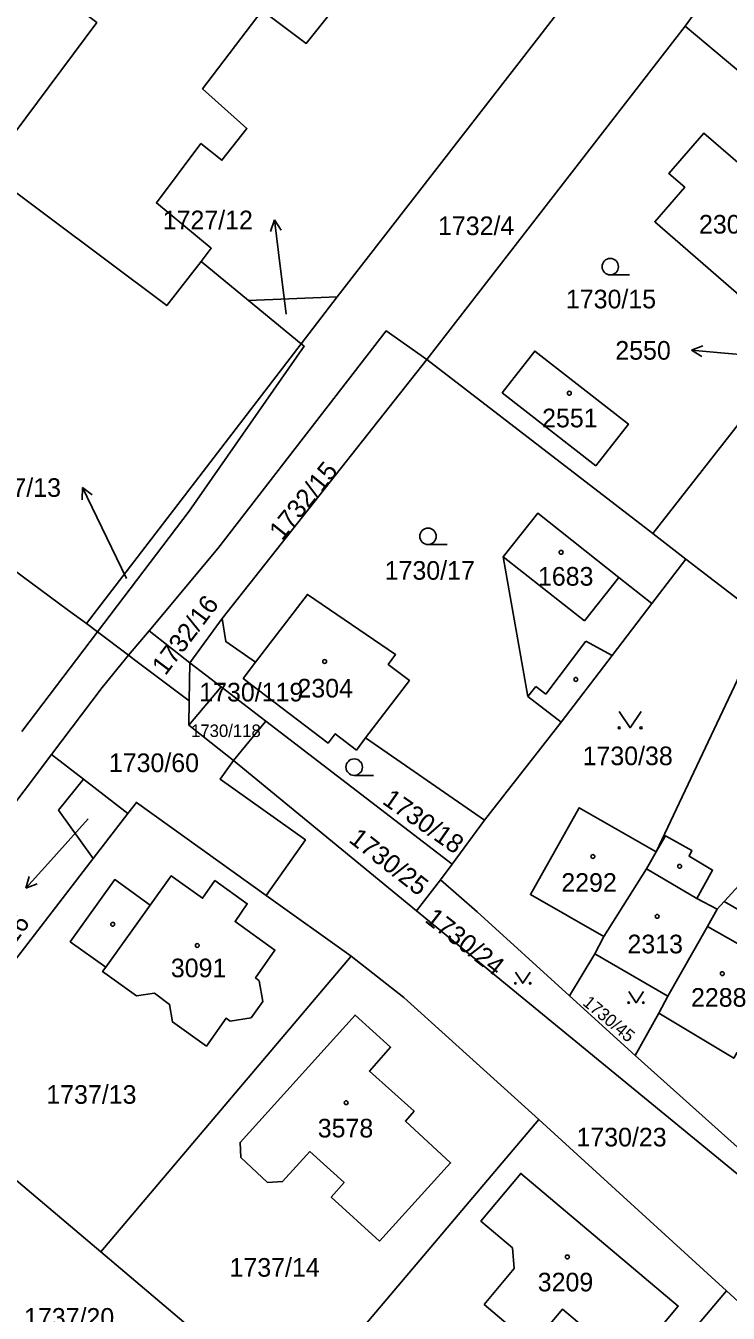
# Model space of a CAD drawing. Extents: x -679220 to -673243, y -1075091 to -1066557.
# Drawn here: x -676884 to -676820, y -1072173.6 to -1072056.2 of the extents above; entities that cross this region are included whole.
import ezdxf

# ---------------------------------------------------------------- set-up
doc = ezdxf.new("R2010")
doc.units = 0
for name, color, linetype in [('Hranice parcel', 7, 'Continuous'), ('Parcelní čísla', 7, 'Continuous'), ('Pop  PČ popisy', 7, 'Continuous'), ('Vnitřní kresba', 7, 'Continuous'), ('Značky budov', 7, 'Continuous'), ('Značky kultur', 7, 'Continuous')]:
    doc.layers.add(name, color=color, linetype=linetype)

msp = doc.modelspace()

# ---------------------------------------------------------------- linework, layer by layer
at = {"layer": 'Hranice parcel'}
for p, q in [((-676823.88, -1072056.2), (-676821.06, -1072052.26)), ((-676847.45, -1072086.6), (-676823.88, -1072056.2)), ((-676803.88, -1072073.07), (-676823.88, -1072056.2)), ((-676868.02, -1072077.66), (-676863.69, -1072081.21)), ((-676863.69, -1072081.21), (-676855.6, -1072080.89)), ((-676858.9, -1072085.15), (-676855.6, -1072080.89)), ((-676858.9, -1072085.15), (-676863.69, -1072081.21)), ((-676878.47, -1072110.68), (-676858.9, -1072085.15)), ((-676866.08, -1072110.22), (-676847.45, -1072086.6)), ((-676847.45, -1072086.6), (-676826.85, -1072102.46)), ((-676816.81, -1072089.62), (-676826.85, -1072102.46)), ((-676826.85, -1072102.46), (-676823.82, -1072104.8)), ((-676823.82, -1072104.8), (-676826.92, -1072108.84)), ((-676823.82, -1072104.8), (-676816.58, -1072110.38)), ((-676869.04, -1072114.25), (-676866.08, -1072110.22)), ((-676826.54, -1072131.48), (-676816.58, -1072110.38)), ((-676877.46, -1072111.44), (-676884.36, -1072120.53)), ((-676877.46, -1072111.44), (-676878.47, -1072110.68)), ((-676874.63, -1072113.57), (-676877.46, -1072111.44)), ((-676874.63, -1072113.57), (-676872.76, -1072111.33)), ((-676872.76, -1072111.33), (-676869.04, -1072114.25)), ((-676869.04, -1072114.25), (-676869.1, -1072117.73)), ((-676866.18, -1072116.45), (-676869.04, -1072114.25)), ((-676866.18, -1072116.45), (-676869.14, -1072119.94)), ((-676862.11, -1072119.58), (-676866.18, -1072116.45)), ((-676869.14, -1072119.94), (-676869.1, -1072117.73)), ((-676862.11, -1072119.58), (-676865.06, -1072123.15)), ((-676845.13, -1072132.63), (-676862.11, -1072119.58)), ((-676835.2, -1072119.66), (-676842.17, -1072128.6)), ((-676820.33, -1072136.02), (-676805.06, -1072119.28)), ((-676865.06, -1072123.15), (-676869.14, -1072119.94)), ((-676853.02, -1072121.11), (-676842.17, -1072128.6)), ((-676878.73, -1072124.88), (-676881.65, -1072122.62)), ((-676848.37, -1072136.87), (-676865.06, -1072123.15)), ((-676878.73, -1072124.88), (-676874.69, -1072128)), ((-676877.85, -1072132.1), (-676874.69, -1072128)), ((-676842.17, -1072128.6), (-676845.13, -1072132.63)), ((-676894.29, -1072153.48), (-676877.85, -1072132.1)), ((-676846.2, -1072134.04), (-676845.13, -1072132.63)), ((-676846.2, -1072134.04), (-676848.37, -1072136.87)), ((-676862.08, -1072135.47), (-676854.34, -1072141.02)), ((-676820.33, -1072136.02), (-676820.97, -1072136.72)), ((-676793.27, -1072182.15), (-676848.37, -1072136.87)), ((-676831.31, -1072139.22), (-676832.14, -1072140.8)), ((-676834.43, -1072144.62), (-676832.14, -1072140.8)), ((-676832.14, -1072140.8), (-676825.48, -1072144.67)), ((-676877.14, -1072167.98), (-676854.34, -1072141.02)), ((-676828.45, -1072150.07), (-676834.43, -1072144.62)), ((-676825.48, -1072144.67), (-676826.29, -1072146.21)), ((-676826.29, -1072146.21), (-676828.45, -1072150.07)), ((-676817.98, -1072159.47), (-676828.45, -1072150.07)), ((-676877.14, -1072167.98), (-676894.29, -1072153.48)), ((-676859.84, -1072182.62), (-676837.24, -1072155.91)), ((-676837.24, -1072155.91), (-676820.13, -1072171.54)), ((-676861.6, -1072181.13), (-676877.14, -1072167.98)), ((-676820.13, -1072171.54), (-676842.16, -1072197.58)), ((-676820.13, -1072171.54), (-676804.75, -1072185.58))]:
    msp.add_line(p, q, dxfattribs=at)
for points in [[(-676868.02, -1072077.66), (-676867.08, -1072076.45), (-676872.09, -1072072.31), (-676868.03, -1072066.91), (-676866.12, -1072068.42), (-676863.83, -1072065.54), (-676867.87, -1072061.91), (-676862.44, -1072054.78), (-676858.43, -1072057.77), (-676851.76, -1072049.4), (-676847.29, -1072052.86), (-676843.34, -1072047.64), (-676857.56, -1072036.75), (-676866.88, -1072047.56), (-676883.62, -1072035.08), (-676891.33, -1072045.54), (-676877.52, -1072055.87), (-676884, -1072064.55)], [(-676855.6, -1072080.89), (-676837.24, -1072057.21), (-676831.2, -1072049.36)], [(-676884, -1072064.55), (-676887.59, -1072069.36), (-676871.15, -1072081.68), (-676868.02, -1072077.66)], [(-676818.55, -1072081.08), (-676812.62, -1072074.24), (-676816.12, -1072071.21), (-676815.04, -1072069.96), (-676817.81, -1072067.56), (-676818.89, -1072068.81), (-676822.18, -1072065.95), (-676825.37, -1072069.64), (-676823.93, -1072070.88), (-676826.67, -1072074.03), (-676818.55, -1072081.08)], [(-676919.29, -1072078.44), (-676919.07, -1072080.61), (-676880.11, -1072109.47), (-676878.47, -1072110.68)], [(-676872.76, -1072111.33), (-676866.49, -1072103.82), (-676851.15, -1072083.99), (-676847.45, -1072086.6)], [(-676858.9, -1072085.15), (-676858.61, -1072085.38), (-676869.11, -1072100.43), (-676877.46, -1072111.44)], [(-676832.03, -1072096.29), (-676829.07, -1072092.48), (-676837.6, -1072085.83), (-676840.56, -1072089.63), (-676832.03, -1072096.29)], [(-676826.92, -1072108.84), (-676829.93, -1072106.46), (-676837.33, -1072100.61), (-676840.48, -1072104.59), (-676838.23, -1072117.32), (-676835.2, -1072119.66)], [(-676853.02, -1072121.11), (-676849.03, -1072115.87), (-676850.96, -1072114.4), (-676850.28, -1072113.51), (-676858.32, -1072108.01), (-676863.04, -1072114.2)], [(-676826.92, -1072108.84), (-676830.56, -1072113.6), (-676835.2, -1072119.66)], [(-676866.08, -1072110.22), (-676865.76, -1072112.32), (-676863.04, -1072114.2)], [(-676881.65, -1072122.62), (-676877.03, -1072116.51), (-676874.63, -1072113.57)], [(-676869.1, -1072117.73), (-676874.09, -1072113.98), (-676874.63, -1072113.57)], [(-676863.04, -1072114.2), (-676864.17, -1072115.68), (-676856.44, -1072121.58), (-676855.79, -1072120.73), (-676853.86, -1072122.21), (-676853.02, -1072121.11)], [(-676881.65, -1072122.62), (-676886.67, -1072129.25), (-676891.41, -1072136.94), (-676900.48, -1072148.99), (-676901.52, -1072159.25), (-676900.62, -1072162.14)], [(-676865.06, -1072123.15), (-676866.28, -1072124.86), (-676858.5, -1072130.41), (-676862.08, -1072135.47)], [(-676877.85, -1072132.1), (-676881.01, -1072127.7), (-676878.73, -1072124.88)], [(-676874.69, -1072128), (-676873.91, -1072126.99), (-676862.08, -1072135.47)], [(-676826.54, -1072131.48), (-676833.54, -1072127.48), (-676838, -1072135.39), (-676831.31, -1072139.22)], [(-676820.97, -1072136.72), (-676822.84, -1072135.74), (-676821.4, -1072133.15), (-676823.54, -1072131.89), (-676823.29, -1072131.36), (-676825.68, -1072130.03), (-676826.54, -1072131.48)], [(-676831.31, -1072139.22), (-676827.43, -1072133.04), (-676826.54, -1072131.48)], [(-676872.26, -1072144.39), (-676870.89, -1072145.41), (-676870.62, -1072147), (-676867.53, -1072149.2), (-676865.73, -1072146.67), (-676865.35, -1072146.95), (-676863.46, -1072146.64), (-676862.38, -1072145.13), (-676862.71, -1072143.26), (-676863.04, -1072142.99), (-676861.28, -1072140.46), (-676864.92, -1072137.85), (-676863.8, -1072136.23), (-676866.76, -1072134.12), (-676867.88, -1072135.73), (-676870.73, -1072133.68), (-676872.64, -1072136.36), (-676875.89, -1072134.03), (-676879.94, -1072139.69), (-676876.7, -1072142.02), (-676876.99, -1072142.42), (-676873.9, -1072144.61), (-676872.26, -1072144.39)], [(-676834.43, -1072144.62), (-676842.84, -1072136.96), (-676846.2, -1072134.04)], [(-676826.29, -1072146.21), (-676819.47, -1072150.32), (-676819.19, -1072149.82), (-676815.71, -1072151.78), (-676809.26, -1072140.45), (-676813.74, -1072137.86), (-676814.6, -1072139.34), (-676820.33, -1072136.02)], [(-676820.97, -1072136.72), (-676821.85, -1072138.29), (-676825.48, -1072144.67)], [(-676854.34, -1072141.02), (-676849.52, -1072144.78), (-676837.24, -1072155.91)], [(-676848.59, -1072155.14), (-676849.39, -1072156.05), (-676845.28, -1072159.86), (-676851.75, -1072166.99), (-676856.15, -1072162.98), (-676854.98, -1072161.64), (-676858.11, -1072158.83), (-676860.58, -1072161.56), (-676861.95, -1072161.64), (-676864.38, -1072159.38), (-676864.46, -1072158), (-676853.97, -1072146.38), (-676850.74, -1072149.31), (-676852.67, -1072151.48), (-676848.59, -1072155.14)], [(-676842.21, -1072172.77), (-676839.47, -1072169.5), (-676839.63, -1072167.61), (-676842.51, -1072165.16), (-676838.87, -1072160.82), (-676824.52, -1072172.92), (-676829.02, -1072178.3), (-676835.07, -1072173.19), (-676837.85, -1072176.48), (-676842.21, -1072172.77)]]:
    msp.add_lwpolyline(points, dxfattribs=at)
at = {"layer": 'Pop  PČ popisy'}
for p, q in [((-676861.32, -1072073.87), (-676861.69, -1072074.93)), ((-676860.95, -1072076.85), (-676861.32, -1072073.87)), ((-676861.32, -1072073.87), (-676860.7, -1072074.8)), ((-676860.26, -1072082.47), (-676860.95, -1072076.85)), ((-676823.31, -1072085.75), (-676822.27, -1072085.34)), ((-676820.32, -1072086.01), (-676823.31, -1072085.75)), ((-676823.31, -1072085.75), (-676822.36, -1072086.33)), ((-676818.14, -1072086.2), (-676820.32, -1072086.01)), ((-676878.83, -1072098.27), (-676878.84, -1072099.39)), ((-676877.51, -1072100.97), (-676878.83, -1072098.27)), ((-676878.83, -1072098.27), (-676877.94, -1072098.95)), ((-676874.82, -1072106.56), (-676877.51, -1072100.97)), ((-676878.31, -1072128.47), (-676881.98, -1072132.59)), ((-676881.98, -1072132.59), (-676883.99, -1072134.82)), ((-676883.99, -1072134.82), (-676883.69, -1072133.74)), ((-676883.99, -1072134.82), (-676882.95, -1072134.41))]:
    msp.add_line(p, q, dxfattribs=at)
at = {"layer": 'Vnitřní kresba'}
for p, q in [((-676833.08, -1072110.44), (-676840.48, -1072104.59)), ((-676833.08, -1072110.44), (-676829.93, -1072106.46)), ((-676836.6, -1072117.11), (-676832.96, -1072112.27)), ((-676832.96, -1072112.27), (-676830.56, -1072113.6)), ((-676838.23, -1072117.32), (-676837.49, -1072116.43)), ((-676837.49, -1072116.43), (-676836.6, -1072117.11)), ((-676827.43, -1072133.04), (-676822.84, -1072135.74)), ((-676876.7, -1072142.02), (-676872.64, -1072136.36)), ((-676821.85, -1072138.29), (-676815.95, -1072141.68))]:
    msp.add_line(p, q, dxfattribs=at)
at = {"layer": 'Značky budov'}
for centre in [(-676834.45, -1072089.67), (-676835.2, -1072104.18), (-676856.75, -1072114.14), (-676833.86, -1072115.77), (-676832.3, -1072131.92), (-676824.4, -1072132.81), (-676826.44, -1072137.38), (-676876.07, -1072138.1), (-676868.36, -1072140.04), (-676820.51, -1072142.6), (-676854.79, -1072154.37), (-676834.63, -1072168.44)]:
    msp.add_circle(centre, 0.175, dxfattribs=at)
at = {"layer": 'Značky kultur'}
for p, q in [((-676830.72, -1072078.88), (-676828.97, -1072078.88)), ((-676847.33, -1072103.47), (-676845.58, -1072103.47)), ((-676854.06, -1072124.52), (-676852.31, -1072124.52))]:
    msp.add_line(p, q, dxfattribs=at)
for points in [[(-676829.91, -1072118.68), (-676828.91, -1072120.18), (-676827.91, -1072118.68)], [(-676839.36, -1072142.47), (-676838.69, -1072143.48), (-676838.02, -1072142.47)], [(-676829.04, -1072144.24), (-676828.37, -1072145.25), (-676827.7, -1072144.24)]]:
    msp.add_lwpolyline(points, dxfattribs=at)
for centre, radius in [((-676830.72, -1072078.13), 0.75), ((-676847.33, -1072102.72), 0.75), ((-676829.91, -1072120.18), 0.1), ((-676827.91, -1072120.18), 0.1), ((-676854.06, -1072123.77), 0.75), ((-676839.36, -1072143.48), 0.067), ((-676838.02, -1072143.48), 0.067), ((-676829.04, -1072145.25), 0.067), ((-676827.7, -1072145.25), 0.067)]:
    msp.add_circle(centre, radius, dxfattribs=at)

# ---------------------------------------------------------------- texts
at = {"layer": 'Parcelní čísla'}
for s, height, p in [('1727/12', 1.7, (-676871.51, -1072074.72)), ('1732/4', 1.7, (-676846.42, -1072075.25)), ('2303', 1.7, (-676822.63, -1072075.11)), ('1730/15', 1.7, (-676834.76, -1072081.93)), ('2550', 1.7, (-676830.26, -1072086.61)), ('2551', 1.7, (-676836.93, -1072092.78)), ('1727/13', 1.7, (-676889, -1072099.12)), ('1730/17', 1.7, (-676851.28, -1072106.68)), ('1683', 1.7, (-676837.31, -1072107.22)), ('1730/119', 1.7, (-676868.18, -1072117.78)), ('2304', 1.7, (-676859.23, -1072117.42)), ('1730/118', 1.14, (-676868.93, -1072121.02)), ('1730/38', 1.7, (-676833.24, -1072123.59)), ('1730/60', 1.7, (-676876.42, -1072124.22)), ('2292', 1.7, (-676835.18, -1072135.14)), ('2313', 1.7, (-676829.15, -1072140.75)), ('3091', 1.7, (-676870.77, -1072142.93)), ('2288', 1.7, (-676823.36, -1072145.62)), ('1737/13', 1.7, (-676882.12, -1072154.47)), ('3578', 1.7, (-676857.38, -1072157.54)), ('1730/23', 1.7, (-676833.8, -1072158.36)), ('1737/14', 1.7, (-676865.42, -1072170.24)), ('3209', 1.7, (-676837.33, -1072171.58)), ('1737/20', 1.7, (-676884.15, -1072174.8))]:
    msp.add_text(s, height=height, dxfattribs=at).set_placement(p)
for s, height, rotation, p in [('1732/15', 1.7, 51, (-676860.63, -1072103.18)), ('1732/16', 1.7, 53, (-676871.27, -1072115.49)), ('1730/18', 1.7, 325, (-676851.59, -1072127.04)), ('1730/25', 1.7, 322, (-676854.64, -1072130.53)), ('1737/16', 1.7, 54, (-676888.38, -1072144.63)), ('1730/24', 1.7, 322, (-676847.71, -1072137.82)), ('1730/45', 1.14, 320, (-676833.31, -1072145.39))]:
    msp.add_text(s, height=height, rotation=rotation, dxfattribs=at).set_placement(p)

doc.saveas('drawing.dxf')
